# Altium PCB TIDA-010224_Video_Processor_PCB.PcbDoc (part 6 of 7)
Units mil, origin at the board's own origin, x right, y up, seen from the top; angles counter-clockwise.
Board outline 2355.46 x 4164 mil, 10 copper layers (L1-Top Layer, L2-GND, L3-SIG1, L4-GND, L5-PWR, L6-PWR, L7-GND, L8-SIG2, L9-GND, L10-Bottom Layer), stack 62.2 mil thick; 508 components, 274 nets, 3619 pads, 705 vias.
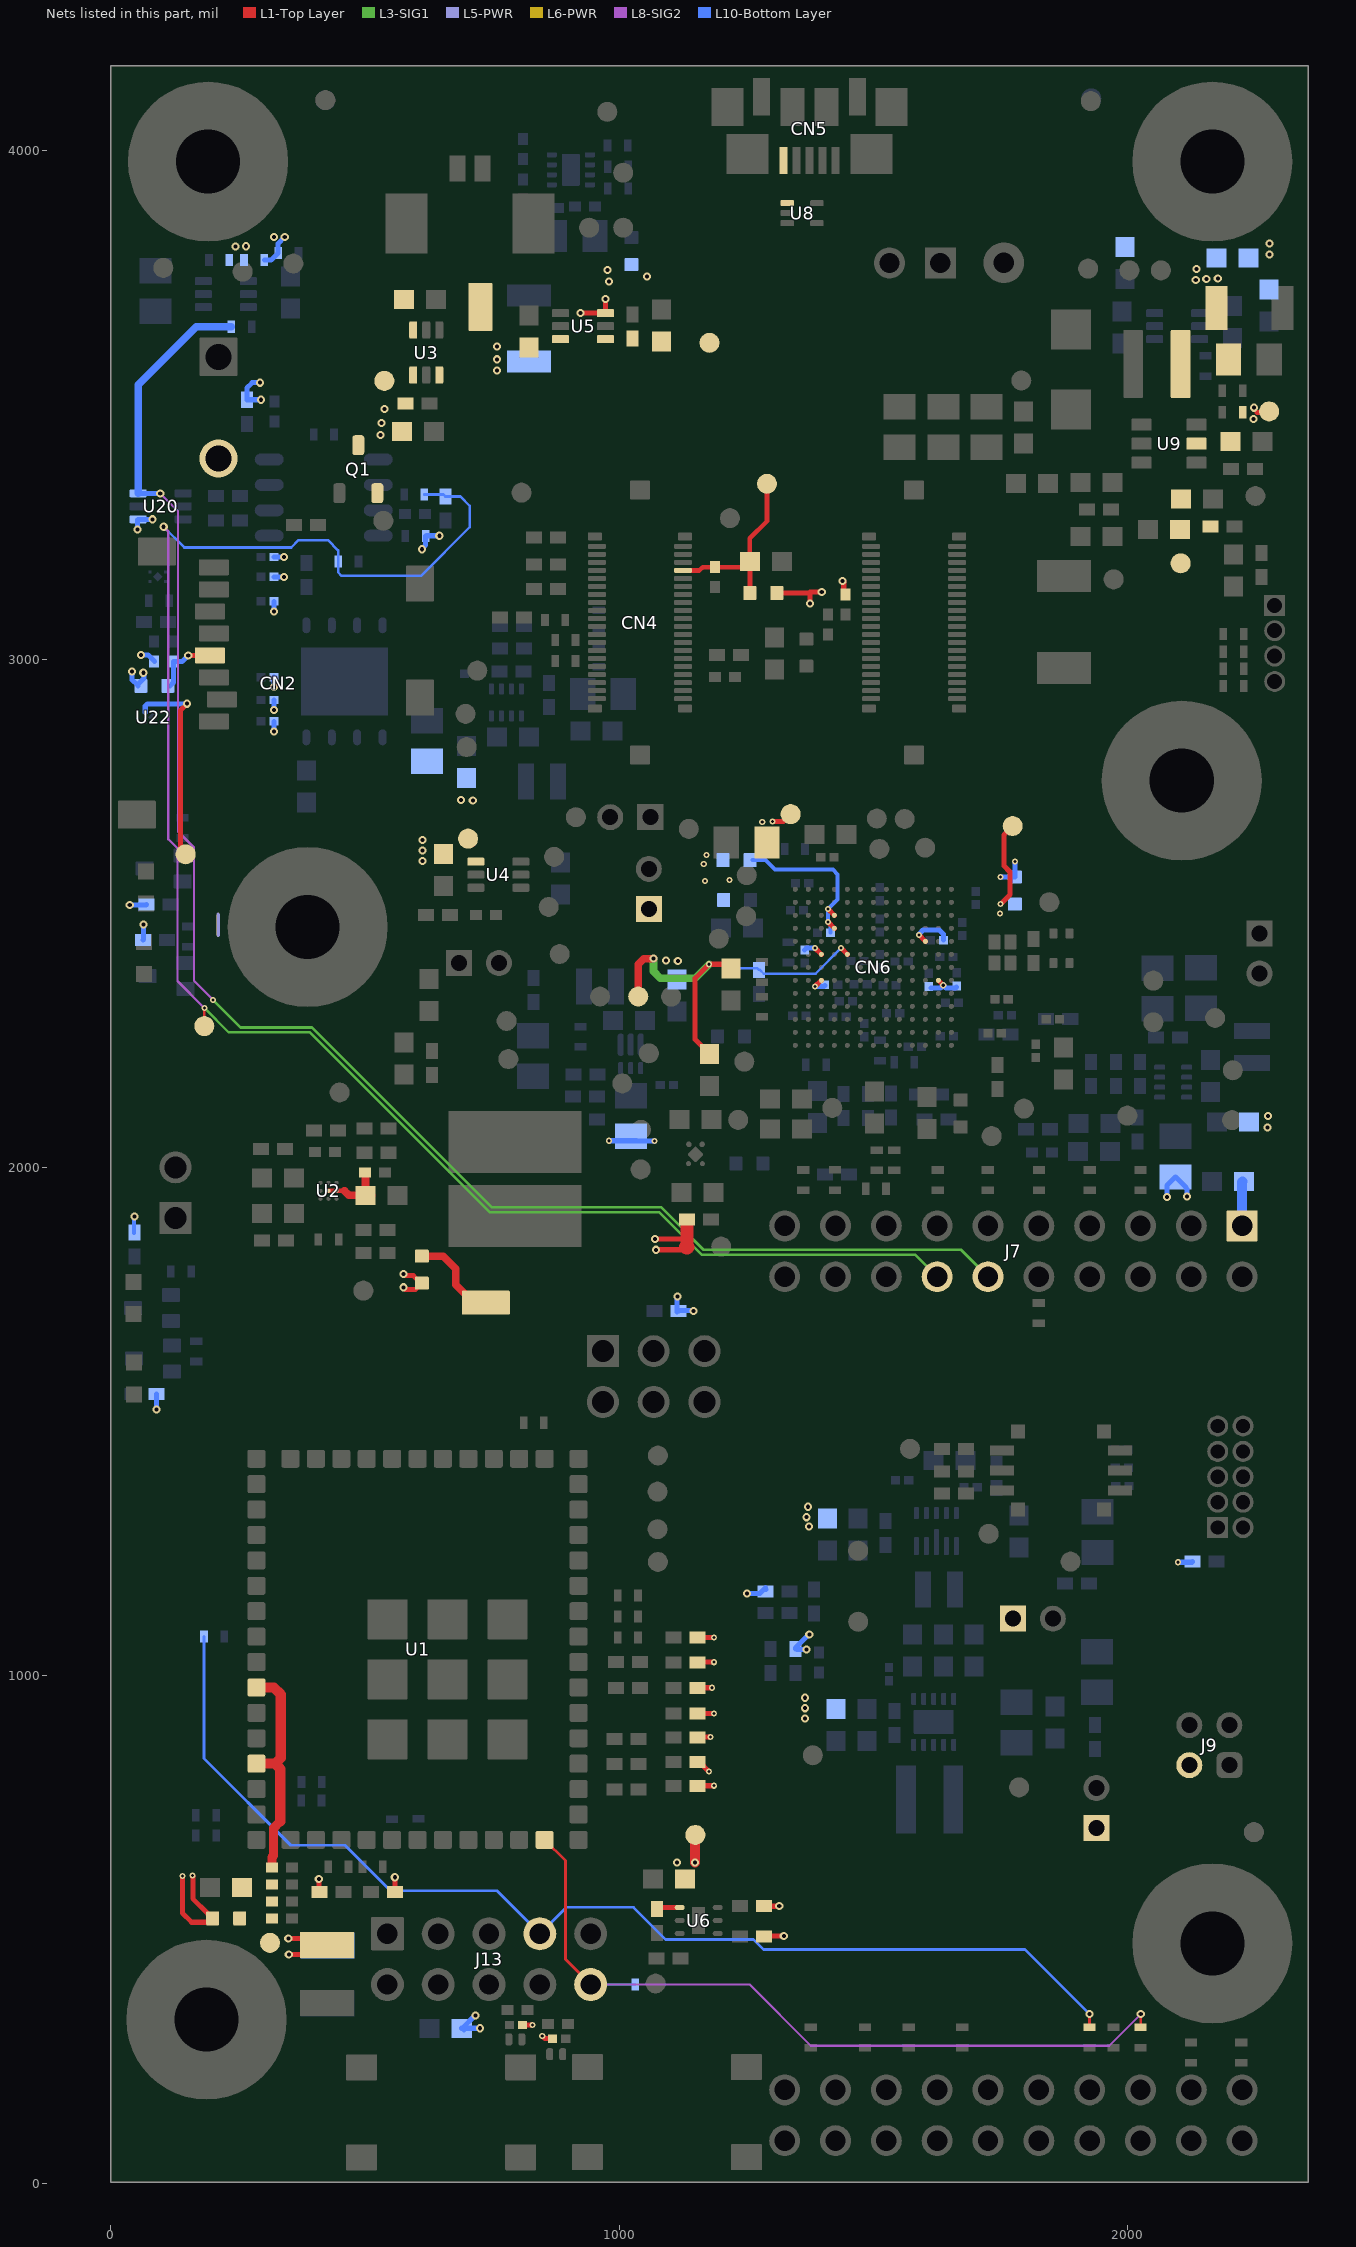
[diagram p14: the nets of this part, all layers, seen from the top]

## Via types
v1: diameter 16, hole 8, L1-Top Layer to L10-Bottom Layer, tented both sides, 414 vias
v2: diameter 12, hole 6, L1-Top Layer to L10-Bottom Layer, tented both sides, 243 vias
v3: diameter 19.68, hole 7.87, L1-Top Layer to L10-Bottom Layer, 44 vias
v4: diameter 14, hole 6, L1-Top Layer to L10-Bottom Layer, tented both sides, 2 vias
v5: diameter 16, hole 8, L1-Top Layer to L10-Bottom Layer, tented top, 1 vias
v6: diameter 20, hole 10, L1-Top Layer to L10-Bottom Layer, tented both sides, 1 vias

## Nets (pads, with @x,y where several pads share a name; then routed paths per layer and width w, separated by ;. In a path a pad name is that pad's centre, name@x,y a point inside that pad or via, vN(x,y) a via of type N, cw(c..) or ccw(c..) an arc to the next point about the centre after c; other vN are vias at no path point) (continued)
V3P3: C41.1 C134.2 FB3.1 FB6.1 FB11.1 FB12.1 J2.1 R182.2 R183.2 | length 404.6
  L1-Top Layer w10: FB3.1@1310.35,3130.18 1374.09,3130.18 1375.77,3131.87 ; v1(1375.77,3109.37) 1375.77,3131.87 ; v1(1398.68,3132) 1375.91,3132 1375.77,3131.87 ; v1@1439.77,3154.77 1441.93,3152.62 1441.93,3128.58 C41.1@1443.27,3127.24
  L5-PWR w6: 210.34,2498.74 211.17,2497.91 211.17,2455.84
  L10-Bottom Layer w10: v1(37,2516) 68.91,2516 R182.2@69.91,2517 ; v1(41.53,2976.03) 41.53,2959.43 FB12.1@53.5,2947.46 ; FB12.1@53.56,2947.46 52,2949.02 65.24,2962.26 v1@65.23,2974.24 ; v1(58.99,3008) 73.27,3008 C134.2@85.52,2995.75 ; R183.2@62.96,2447 64,2448.04 v1(64,2478) ; v2(1750,2571.63) 1750.2,2571.43 FB6.1@1778.52,2571.43 v2@1778.52,2600.79
  other v1: 63.66,2973.3 1439.64,3153.47 980,3742.87 1054.83,3753.11 977.26,3766
  other v2: 1779.24,2601.51
V3P3_Amp: R153.2 R169.2 R174.2 | length 55.1
  L10-Bottom Layer w10: v1@612.36,3217.89 612.69,3217.89 619.25,3224.45 R153.2@619.25,3242.41 619.79,3241.87 620.81,3242.89 v1(646.11,3242.89)
  other v1: 612.07,3216.2 245,3812 266,3812.53
V3P3_MCU: 3.3V_MCU.1 C3.1 C4.2 C5.2 C6.2 C7.1 C24.1 C61.2 C127.1 FB1.2 J7.1 J9.3 R1.1 R6.1 R11.1 R16.2 R22.2 R34.2 R35.1 R36.1 R37.1 R38.1 R39.1 R40.1 R43.1 R44.1 R89.1 R133.1 R151.1 R162.1 R169.1 R185.2 R186.2 R187.2 U1.37 U1.40 U6.1 VCC_ALS.1 | length 1660.8
  L1-Top Layer w10: v1(349,483) 411.87,483 C7.1@424.85,470.02 406.32,451.49 v1(350,451.49) ; v1(409.02,599.83) 409.02,576.22 R6.1@410.76,574.47 ; v1(558.57,603.16) 558.57,574.54 558.86,574.25 R11.1@559.08,574.47 ; R16.2@810.61,312.74 v2@829.55,312.74 ; v2(848.64,291) 853.94,285.7 R22.2@869.02,285.7 R22.2@872.7,285.7 ; R34.2@1074.95,541.06 1077.63,543.74 U6.1@1119.17,543.74 ; R36.1@1147.26,879.26 v2(1179.37,879.26) ; R39.1@1154.62,830 1158,830 v2(1177,811) ; R187.2@1154.62,1075 v2(1186.74,1075) ; R40.1@1154.88,783.26 v2(1187,783.26) ; R37.1@1154.88,925.49 v2(1187,925.49) ; R38.1@1154.88,975.9 1155.78,975 1156.78,976 v2(1183,976) ; R35.1@1154.88,1026.31 v2(1187,1026.31) ; R43.1@1285.24,546.15 1314.71,546.15 v1(1315,546.44) ; R44.1@1285.47,488.56 1286.47,487.56 v1(1323.99,487.56)
  L1-Top Layer w18: C3.1@316.63,622.67 316.63,642.63 320,646 320,700 333,713
  L1-Top Layer w20: U1.40@286.33,826.67 322.8,826.67 ; U1.37@286.33,976.67 320.33,976.67 334,963 334,837.87 322.8,826.67 ; 333,713 333,816.46 322.8,826.67 ; v1(1149.16,632.44) VCC_ALS.1@1149.16,677.35
  L6-PWR w6: 211.18,2495.33 211.18,2457.68 211.61,2457.25
  L10-Bottom Layer w8: R186.2@45.78,1870.98 45.78,1906.47 46,1906.25 v1(46,1903) ; v1(349,483) 421.71,483 C127.1@424.85,479.86 ; v1(350,451.49) 391.49,451.49 392.7,452.7 C127.1@392.7,480.37
  L10-Bottom Layer w10: v1(89.58,1523.76) R185.2@89.58,1553.71 ; R169.1@301.76,3785.12 314.94,3785.12 R162.1@329.04,3799.21 329.04,3818 v1(342.04,3831) ; R151.1@690.28,306 R151.1@691.5,306 ; v1(717,331) 716.5,331 R151.1@691.5,306 ; v1(726,306) 697.5,306 694.5,303 R151.1@691.5,306 ; R133.1@1114.21,1715.35 v1@1114.21,1740.97 ; R133.1@1117.21,1717.35 1118.04,1718.17 1145.18,1718.17 v1(1146.01,1717.35) ; v2(2099.33,1223) 2127.41,1223 R89.1@2128.41,1224
  L10-Bottom Layer w20: J7.1@2225.78,1884.79 2225.78,1971.5 C61.2@2226.43,1972.15
  other v1: 1113.95,632.44 1114.59,1745.9 320.53,3831
  other v2: 829.55,312.24
V3P3_OV: C79.2 C82.2 C83.2 C100.2 C107.2 CN6.F2 CN6.F11 CN6.H11 CN6.J3 FB6.2 FB8.1 FB9.1 OV_3.3V.1 | length 405.2
  L1-Top Layer w10: v2(1385.59,2355.77) CN6.F11@1397.82,2368 ; v2(1385.59,2431.41) CN6.H11@1397.82,2419.18 ; v2(1590.32,2457) CN6.J3@1602.54,2444.77 ; CN6.F2@1628.13,2368 v2(1637.77,2358.36) ; v2(1750.34,2517.85) 1769.07,2536.58 1769.07,2581.41 1757.06,2593.42 1757.06,2654.33 OV_3.3V.1@1774.34,2671.61
  L10-Bottom Layer w10: C107.2@1365,2427.99 1368.42,2431.41 v2(1385.59,2431.41) ; v2(1385.59,2355.77) 1402.78,2355.77 C100.2@1405.01,2358 ; v2(1590.32,2457) 1590.32,2459.36 1597.98,2467.03 1629.64,2467.03 1637.99,2458.68 C82.2@1637.99,2447 ; C83.2@1614,2353.01 1632.42,2353.01 v2(1637.77,2358.36) 1643.19,2352.94 1661.93,2352.94 C79.2@1664,2355.01
  other v2: 1749,2499.59 1168.73,2563.6 1216.75,2565.46 1166.46,2596.89 1172,2615
V3P3_PA: 3.3V_PA.1 C9.1 C12.2 FB2.2 U2.B1 U2.B2 | length 308.2
  L1-Top Layer w8: U2.B2@428.07,1953.93 U2.B1@443.82,1953.93 459.47,1953.93
  L1-Top Layer w15: 459.47,1953.93 468.4,1945 C9.1@485,1945 ; C9.1@500.96,1950.4 C12.2@500.96,1983.17 ; FB2.2@611.6,1825.15 653.59,1825.15 678.16,1800.58 678.16,1769.21 713.61,1733.76 3.3V_PA.1@737.57,1733.76 ; C9.1@496.71,1944.34 513.02,1944.34 C9.1@496.71,1944.34
V3P3_SC: 3.3V_SC.1 C131.2 CN2.4 FB12.2 R163.2 R164.2 R165.2 R166.2 R167.2 R168.2 U22.4 | length 647.5
  L1-Top Layer w10: 3.3V_SC.1@146.92,2616 137,2625.92 137,2899.33 v1(150,2912.33) ; v1(152.16,3007.36) CN2.4@194.65,3007.36
  L10-Bottom Layer w10: U22.4@67.52,2895.44 67.52,2907.35 72.17,2912 149.67,2912 v1(150,2912.33) ; FB12.2@116.52,2947.44 123,2953.91 123,2995 139.8,2995 v1(152.16,3007.36) ; v1(321,2858) R166.2@321,2877.71 ; v1(321,2900) R165.2@321,2919.71 ; v1(321,2945) R164.2@321,2964.71 ; v1(321,3094) R163.2@321,3113.71 ; R168.2@320.99,3162 v1(340.7,3162) ; R167.2@320.99,3201 v1(340.7,3201)
V3P3_SN_AVDD: AVDD.1 C30.1 C34.1 CN4.8 FB3.2 | length 368
  L1-Top Layer w9: CN4.8@1125.65,3174.49 1157.79,3174.49 1164.3,3181 1245.17,3181 C34.1@1257.2,3193.03 ; C34.1@1257.2,3192.03 C34.1@1257.2,3193.03 ; AVDD.1@1290.89,3345 1290.89,3271.56 1257.2,3237.87 C34.1@1257.2,3193.03
  L1-Top Layer w10: FB3.2@1257.2,3130.18 C34.1@1257.2,3192.03
V3P3A: C18.1 FB1.1 FB2.1 IN_3.3V.1 J4.1 J10.1 R127.2 R128.2 U4.1 | length 449.2
  L1-Top Layer w10: v2(140.47,606) 140.47,533.03 158.86,514.64 192.07,514.64 192.31,514.88 192.92,514.88 FB1.1@200.22,522.18 199.61,522.18 189.79,532 189.79,532.4 161.14,561.05 161.14,605.21 v2(160.1,606.24) ; v1(575.32,1764) 579.32,1760 599.6,1760 FB2.1@608.29,1768.69 ; v1(575.32,1790.31) 578.76,1786.87 594.87,1786.87 609.73,1772 FB2.1@611.6,1772 ; IN_3.3V.1@702.69,2646.83 IN_3.3V.1@712.99,2636.53
  L10-Bottom Layer w10: v1(1251.51,1161.38) 1276.61,1161.38 R128.2@1286.47,1171.23 ; R128.2@1288,1172.76 R128.2@1286.47,1171.23 ; R128.2@1288.73,1168.97 R128.2@1286.47,1171.23 ; R127.2@1346.84,1052.47 R127.2@1346.84,1054.66 ; v1(1368.79,1051.66) 1350.21,1051.66 1350.03,1051.47 R127.2@1346.84,1054.66 ; v1(1374.19,1080.66) 1372.84,1080.66 R127.2@1346.84,1054.66
  other v1: 613,2602.79 613,2623.79 613,2644
V_POWER: C57.1 C58.1 L1.1 R88.2 R95.2
  other v1: 2134.51,3746.1 2155.33,3747.73 2177.98,3749.15 2136.25,3767.97
V_VBAT: BAT.1 C13.1 C16.1 Q1.2 U3.1 U5.3 U20.1 | length 125.5
  L1-Top Layer w10: v1(924,3681) 973.17,3681 v1(973.17,3708.76)
  L10-Bottom Layer w10: v1(52.41,3255) 52.41,3274.1 U20.1@53.49,3275.17 v1(81.49,3275.17)
  other v1: 530.17,3440.79 532.14,3465 538.42,3492
VBAT: C14.1 C21.1 C59.2 C119.1 R41.2 R79.2 R86.1 R87.1 R88.1 R91.2 R123.1 R124.1 R134.1 R137.2 R150.1 R152.2 R170.2 U3.6 U5.6 U9.5 VBAT.1 VP.1 | length 457.9
  L1-Top Layer w10: v1(1070.63,1859.05) 1126.13,1859.05 ; v1(1072.29,1837.83) 1127.79,1837.83 1133.02,1843.06 ; 2255,3485 2276.55,3485 VP.1@2279,3487.45
  L1-Top Layer w25: 1133.38,1843.42 R41.2@1133.38,1892.09
  L1-Top Layer w30: 1133.02,1843.06 1133.38,1843.42
  L10-Bottom Layer w10: v1(293.23,3544) 278.05,3544 267.38,3533.33 R170.2@267.38,3510.43 v1(295.38,3510.43) ; v2(980,2052.38) 1033.62,2052.38 1034,2052 v2(1069.58,2052) ; v1@2077.97,1941.33 2077.97,1964.61 R91.2@2094.44,1981.08 ; R91.2@2095,1981.08 2115.73,1960.36 2115,1959.63 2117,1957.63 v1(2117,1943)
  other v1: 1365.39,915.34 1365.87,935.79 1365.87,956.34 1373.88,1293.21 1368.88,1311.66 1371.88,1332.21 2077.67,1941.33 2275.74,2078.29 2276.74,2101.29 1092.41,2407 1115.41,2406.29 712,2722 689,2723 2248.31,3472.3 2249,3494.8 760,3568 760,3590 760,3615 2279.5,3795.88 2280,3818
VBAT_Gauge: C125.1 J7.27 MEAS_MCU.1 R154.2 R157.2 | length 3536.2
  L1-Top Layer w5.5: MEAS_MCU.1@183.72,2278 v2(183.72,2313.83)
  L3-SIG1 w5: v2(183.72,2313.83) 231.84,2265.7 391.39,2265.7 745.15,1911.94 1078.52,1911.94 1162.3,1828.17 1582.39,1828.17 J7.27@1625.78,1784.79
  L8-SIG2 w4.5: v1(103.83,3260.54) 113,3251.37 113,2645.76 131,2627.76 131,2366.54 v2(183.72,2313.83)
  L10-Bottom Layer w5: v1(103.83,3260.54) 144.65,3219.72 354.84,3219.72 369.45,3234.33 426.67,3234.33 447,3214 R157.2@447,3192 447,3171 454,3164 610.25,3164 706,3259.75 706,3301.54 687.51,3320.03 C125.1@658.25,3320.03 654.28,3324.01 R154.2@616.81,3324.01
VBAT_Meas: J7.26 R171.1 U20.3 | length 3277.9
  L3-SIG1 w5.5: v2(201.11,2329.14) 254.8,2275.45 395.43,2275.45 749.19,1921.69 1082.56,1921.69 1166.33,1837.92 1586.43,1837.92 1586.5,1837.86 1672.71,1837.86 J7.26@1725.78,1784.79
  L8-SIG2 w4.5: v1(97,3326) 131.93,3291.07 131.93,2660.91 163.25,2629.59 163.25,2367 v2(201.11,2329.14)
  L10-Bottom Layer w10: U20.3@53.49,3326.35 53.84,3326 v1(97,3326)
  L10-Bottom Layer w15: U20.3@53.49,3326.35 54,3326.87 54,3540 168,3654 R171.1@237,3654
VBAT_Primary: J1.2 Q1.3
VDDAO: C31.2 C101.2 CN6.K10 CN6.L10 FB9.2 VDDAO.1 | length 379.8
  L1-Top Layer w10: v2(1301.74,2680.48) 1322.86,2680.48 VDDAO.1@1337.44,2695.06 ; v2(1411.18,2482.59) CN6.K10@1423.41,2470.36 ; v2(1411.18,2508.18) CN6.L10@1423.41,2495.95
  L10-Bottom Layer w8: FB9.2@1262.5,2604.55 1288.18,2604.55 1306.6,2586.13 1420.45,2586.13 1430,2576.57 1430,2527 v2(1411.18,2508.18) v2(1411.18,2482.59) 1416.06,2477.71 C101.2@1416.06,2462
  other v2: 1281.62,2679.93
VEFUSE: C33.1 CN6.H9 R42.2 R132.2 VeFuse.1 | length 799.4
  L1-Top Layer w10: R42.2@1178.12,2223.08 1149.65,2251.56 1149.65,2372.35 v2(1176.98,2399.69) 1212.45,2399.69 C33.1@1220.46,2391.68 ; v2(1436.77,2431.41) CN6.H9@1449,2419.18
  L1-Top Layer w15: VeFuse.1@1037.58,2336.15 1037.58,2400.01 1048.26,2410.69 v1(1067.56,2410.69)
  L3-SIG1 w15: v1(1067.56,2410.69) 1067.56,2386.17 1081.28,2372.45 1149.74,2372.45 v2(1176.98,2399.69)
  L10-Bottom Layer w5: v2(1176.98,2399.69) 1177.98,2398.69 1227.74,2398.69 1234.74,2391.68 1271.87,2391.68 R132.2@1274.94,2388.62 ; R132.2@1276.94,2388.62 1284.58,2380.98 1386.34,2380.98 v2(1436.77,2431.41)
VREF: C56.2 R72.1 R76.2 REF.1
VUSB_5V: C23.1 C25.1 CN5.1 U3.3 U5.1 U8.1 USB.1
WIFI_CONFIG: J13.10 R73.1 R136.1 U1.54 | length 1591
  L1-Top Layer w5.5: U1.54@853.26,676.7 894.19,635.77 894.19,441.81 J13.10@944,392 ; R73.1@2025.59,310.73 2026.3,311.44 v1(2026.3,333.73)
  L8-SIG2 w4.5: J13.10@944,392 1256.83,392 1377.02,271.81 1964.39,271.81 v1(2026.3,333.73)
  L10-Bottom Layer w4.5: J13.10@944,392 R136.1@1031.7,392
WIFI_nRESET: J13.7 R69.1 R175.1 | length 2259
  L1-Top Layer w5.5: R69.1@1925.78,308.7 v1(1925.78,333.73)
  L10-Bottom Layer w5.5: R175.1@183.09,1076.67 183.09,836.91 353.88,666.12 460.67,666.12 550.15,576.64 759.36,576.64 J13.7@844,492 896,544 1028,544 1091.38,480.62 1264.38,480.62 1284,461 1798.51,461 v1(1925.78,333.73)
pads on no net: CN3.3 CN3.4 CN4. CN4.3 CN4.4 CN4.6 CN4.10 CN4.11 CN4.12 CN4.13 CN4.15 CN4.27 CN4.29 CN4.31 CN4.33 CN4.35 CN4.37 CN5.4 CN6.A5 CN6.B3 CN6.B9 CN6.C6 CN6.D10 CN6.D11 CN6.D12 CN6.E10 CN6.E11 CN6.E12 CN6.E13 CN6.F10 CN6.F12 CN6.G10 CN6.G12 CN6.G13 CN6.H10 CN6.H12 CN6.H13 CN6.J10 CN6.J11 CN6.J12 CN6.J13 CN6.K7 CN6.K8 CN6.K13 CN6.L4 CN6.L5 CN6.M4 CN6.M5 CN6.M7 CN6.M8 CN6.N4 CN6.N5 CN6.N7 CN6.N8 CN7. CN7.1 CN7.2 CN7.3 CN7.4 CN7.5 CN7.6 CN7.7 CN7.8 CN7.9 CN7.10 CN7.11 CN7.12 CN7.13 CN7.14 CN7.15 CN7.16 CN7.17 CN7.18 CN7.19 CN7.20 CN7.21 CN7.22 CN7.23 CN7.24 CN7.25 CN7.26 CN7.27 CN7.28 CN7.29 CN7.30 CN7.31 CN7.32 CN7.33 CN7.34 CN7.35 CN7.36 CN7.37 CN7.38 CN7.39 CN7.40 D5.1S D5.2S D6.1S D6.2S FID1.1 FID2.1 FID3.1 FID6.1 FID6_1.1 FID6_2.1 H1.1 H2.1 H3.1 H4.1 H5.1 H6.1 H7.0 H8.0 H9.0 H10.0 H11.0 H12.0 J5.10 J7.2 J7.21 J7.23 J7.24 J7.28 J7.29 J7.30 J8.11 J8.16 J8.17 J8.19 J8.31 J8.32 J8.33 J8.34 J8.35 J8.36 LBL1.0 SW3.M1 SW3.M2 SW3.M3 SW3.M4 U1.20 U1.31 U1.33 U1.39 U1.41 U1.45 U1.55@758.77,896.15 U1.55@802.08,896.15 U1.56@758.77,970.96 U1.56@758.77,1014.26 U1.56@802.08,970.96 U1.56@802.08,1014.26 U1.57@758.77,1089.07 U1.57@758.77,1132.37 U1.57@802.08,1089.07 U1.57@802.08,1132.37 U1.58@640.66,852.85 U1.58@640.66,896.15 U1.58@683.97,852.85 U1.58@683.97,896.15 U1.59@640.66,970.96 U1.59@640.66,1014.26 U1.59@683.97,970.96 U1.59@683.97,1014.26 U1.60@640.66,1089.07 U1.60@640.66,1132.37 U1.60@683.97,1089.07 U1.60@683.97,1132.37 U1.61@522.55,852.85 U1.61@522.55,896.15 U1.61@565.86,852.85 U1.61@565.86,896.15 U1.62@522.55,970.96 U1.62@522.55,1014.26 U1.62@565.86,970.96 U1.62@565.86,1014.26 U1.63@522.55,1089.07 U1.63@522.55,1132.37 U1.63@565.86,1089.07 U1.63@565.86,1132.37 U3.4 U4.4 U5.4 U8.2 U10.4 U10.5 U11.4 U13.11@1597.54,908.87 U13.11@1640.46,908.87 U14.4@1003.11,2241.47 U14.5@1022.79,2241.47 U14.6@1042.48,2241.47 U15.9@905,3945.26 U15.9@905,3980.69 U16.4 U18.1 U18.5 U18.8 U19.4 U19.5 U20.4 U20.5
copper on no net: | length 1.4
  L1-Top Layer w5.5: 1325,185.57 1325.78,184.79 ; 1625.78,184.79 1626,185.01

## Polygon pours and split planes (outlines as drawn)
GND on L10-Bottom Layer "L10-BOTTOM_LAYER_GND_P594" (solid, remove dead copper, pour order 594): 2313.77,36.98 13.27,36.98 13.27,4076.27 87,4150 2240.45,4150 2325.78,4064.67 2325.78,48.99
V1P1_OV on L10-Bottom Layer "L10-BOTTOM_LAYER_V1P1_OV_P508" (solid, pour order 508): 1268.7,2031.58 1268.7,1984.05 1278.03,1974.72 1346.33,1974.72 1389.16,2017.55 1389.16,2037.44 1378.71,2047.9 1285.01,2047.9
no net on L10-Bottom Layer "L10-BOTTOM_LAYER_NONET_P647" (solid, pour order 647): 4363.73,1594.74
no net on L10-Bottom Layer "L10-BOTTOM_LAYER_NONET_P645" (solid, pour order 645): 4364.19,1621.74
no net on L10-Bottom Layer "L10-BOTTOM_LAYER_NONET_P643" (solid, pour order 643): 4358.58,1625.36
no net on L10-Bottom Layer "L10-BOTTOM_LAYER_NONET_P641" (solid, pour order 641): 4363.19,1628.07
NetC69_2 on L10-Bottom Layer "L10-BOTTOM_LAYER_NETC69_2_P521" (solid, pour order 521): 1954.38,2182.14 1953.88,2181.64 1917.34,2181.64 1912.25,2176.55 1912.25,2145.17 1918.66,2138.77 1949.99,2138.77 2036.32,2138.77 2047.85,2150.29 2075.11,2150.29 2077.11,2152.29 2077.11,2163.29 2074.11,2166.29 2017.69,2166.29 2001.85,2182.14
PG_1V8 on L10-Bottom Layer "L10-Bottom Layer-PG_1V8" (solid, remove dead copper, pour order 629): 752.46,2877 657.44,2877 655.56,2875.11 655.56,2854.28 654.28,2853 572.06,2853 568,2857.06 568,2922.93 576.07,2931 648.78,2931 677,2902.78 752.39,2902.78 754,2901.17 754,2878.29 753,2877.29
no net on L10-Bottom Layer "L10-Bottom Layer-No Net" (solid, remove dead copper, pour order 614): 1497,2238.5 1488.5,2247 1470.18,2247 1468.99,2245.81 1468.99,2218.38 1476.05,2211.32 1538.25,2211.32 1538.5,2211.57 1538.5,2237.25 1533.74,2242 1503.22,2242 1498.22,2247 1488,2247
no net on L10-Bottom Layer "L10-Bottom Layer-No Net 1" (solid, remove dead copper, pour order 613): 1533.96,2294.92 1577.89,2294.92 1578.4,2294.41 1578.4,2258.57 1576.63,2256.8 1525.12,2256.8 1519.77,2262.16 1519.77,2296.3 1520,2296.52 1521.67,2294.86 1535,2294.86
V_POWER on L10-Bottom Layer "L10-BOTTOM_LAYER_V_POWER_P583" (solid, pour order 583): 2027,3833.07 2042.66,3833.07 2061.35,3814.38 2193.04,3814.38 2200.89,3806.53 2200.89,3755.5 2178.55,3733.29 2064.34,3733.29 2021.7,3775.94 1964.48,3775.94 1950.26,3790.16 1950.26,3817.35 1965.98,3833.07
VBAT on L10-Bottom Layer "L10-BOTTOM_LAYER_VBAT_P561" (solid, pour order 561): 2299.03,3709.25 2302.78,3713 2302.78,3754.11 2301.7,3755.19 2301.7,3820.09 2296,3826 2225,3826 2217.75,3818.75 2217.75,3750.97 2259.47,3709.25
NetC111_1 on L10-Bottom Layer "L10-Bottom Layer-NetC104_1" (solid, remove dead copper, pour order 599): 849,2957.18 849,2926.19 850.19,2925 877.16,2925 903,2899.16 953.13,2899.16 954,2900.03 954,2962.45 952.45,2964 880,2964 874,2958 849.82,2958
NetC65_1 on L10-Bottom Layer "L10-Bottom Layer-NetC97_1" (solid, remove dead copper, pour order 598): 2030.4,2350.82 2028,2348.42 2028,2256 2035.06,2248.94 2076.7,2248.94 2077,2249.24 2077,2282.44 2096,2301.44 2096,2349.82 2095,2350.82
NetC73_1 on L10-Bottom Layer "L10-BOTTOM_LAYER_NETC73_1_P533" (solid, pour order 533): 1746.53,1209.57 1795.92,1209.57 1819.49,1186 1819.49,1076.98 1826.13,1070.34 1887.81,1070.34 1895.17,1077.71 1895.17,1266.76 1883.91,1278.01 1660.23,1278.01 1655.3,1273.09 1655.3,1237.55 1667.14,1225.71 1730.39,1225.71
NetC70_1 on L10-Bottom Layer "L10-BOTTOM_LAYER_NETC70_1_P513" (solid, remove dead copper, pour order 513): 17 vertices, not listed, extent 1652.04,753.02 1968,897.31
V3P3_MCU on L10-Bottom Layer "L10-Bottom Layer-V3P3_MCU" (solid, remove dead copper, pour order 504): 291.06,3772.17 293.23,3770 322.98,3770 353.57,3800.6 353.57,3842.54 350.04,3846.07 314.28,3846.07 291.06,3822.85
VDDAO on L10-Bottom Layer "L10-BOTTOM_LAYER_VDDAO_P579" (solid, pour order 579): 1261.85,2582 1244,2582 1237,2589 1237,2686.7 1300.65,2686.7 1307.19,2680.16 1307.19,2594.3 1294.89,2582 1244,2582
V3P3_OV on L10-Bottom Layer "L10-BOTTOM_LAYER_V3P3_OV_P507" (solid, pour order 507): 1160.93,2614.72 1172.21,2626 1217,2626 1223,2620 1223,2565.46 1223,2506.65 1213.82,2497.47 1165.45,2497.47 1160.93,2501.99
V3P3_Amp on L10-Bottom Layer "L10-Bottom Layer-V3P3_Amp" (solid, remove dead copper, pour order 506): 220,3774.43 223,3771.43 270.22,3771.43 277.26,3778.47 277.26,3816.86 274.12,3820 225,3820 220,3815
NetC129_2 on L10-Bottom Layer "L10-BOTTOM_LAYER_NETC129_2_P550" (solid, pour order 550): 299.08,3756.65 314.72,3756.65 350.98,3792.9 350.98,3811.74 358.45,3819.21 384.54,3819.21 405,3798.75 405,3733.11 400.89,3729 298.23,3729 293.23,3734 253.72,3734 249.27,3738.46 249.27,3751.42 254.49,3756.65
V3P3 on L10-Bottom Layer "L10-BOTTOM_LAYER_V3P3_P582" (solid, pour order 582): 1745.27,2609.27 1794.27,2609.27 1803.45,2600.08 1803.45,2552.86 1798.69,2548.09 1750,2548.09 1740.69,2557.4 1740.69,2604.69
NetL5_1 on L10-Bottom Layer "L10-BOTTOM_LAYER_NETL5_1_P510" (solid, pour order 510): 19 vertices, not listed, extent 976,2214.89 1048.25,2402.63
NetC114_2 on L10-Bottom Layer "L10-BOTTOM_LAYER_NETC114_2_P509" (solid, pour order 509): 988.8,2202.73 949.18,2202.73 943.82,2197.38 943.82,2081.28 945.11,2080 975,2080 978.31,2083.31 978.31,2166.81 993.81,2182.31 1006.99,2182.31 1011.03,2186.35 1011.03,2208.3 1008.92,2210.42 996.47,2210.42 995.54,2209.46
NetL4_2 on L10-Bottom Layer "L10-BOTTOM_LAYER_NETL4_2_P534" (solid, pour order 534): 1654.96,1201.17 1654.96,1134.11 1662.39,1126.69 1675.17,1126.69 1683.3,1134.81 1683.3,1201.93 1670.02,1215.21 1651.89,1233.35 1651.88,1273.67 1648.88,1276.67 1638.88,1276.67 1636.88,1274.67 1636.88,1219.24
NetC126_2 on L10-Bottom Layer "L10-BOTTOM_LAYER_NETC126_2_P591" (solid, remove dead copper, pour order 591): 491.7,3304.34 561.37,3304.34 565.76,3308.74 594.55,3308.74 598.32,3304.97 598.32,3238.94 588.73,3229.35 570.4,3229.35 562.69,3237.06 562.69,3270.65 551.75,3281.6 495.64,3281.6 491.7,3285.54
NetC62_1 on L10-Bottom Layer "L10-BOTTOM_LAYER_NETC62_1_P511" (solid, pour order 511): 2261.84,3636.02 2298.21,3636.02 2306.34,3644.15 2306.34,3680.55 2299.66,3687.23 2253.57,3687.23 2219.74,3721.05 2171.23,3721.05 2125.48,3721.05 2118.46,3714.03 2118.46,3681.13 2126.96,3672.63 2225.23,3672.62
NetC68_1 on L10-Bottom Layer "L10-BOTTOM_LAYER_NETC68_1_P512" (solid, remove dead copper, pour order 512): 1978.87,906.46 1978.87,996.16 1965.11,1009.92 1906.26,1009.92 1896.17,999.83 1896.17,902.8 1911.84,887.14 1959.55,887.14
NetC110_1 on L10-Bottom Layer "L10-BOTTOM_LAYER_NETC110_1_P515" (solid, pour order 515): 1081.62,2278.3 1054.36,2251.04 1054.36,2229 1054.28,2220.49 1049.37,2215.59 1038.85,2215.59 1035.21,2219.23 1035.21,2310.19 1054.01,2329 1124.63,2329 1127.63,2326 1127.59,2284.3 1121.59,2278.3
Net1.8V_1 on L10-Bottom Layer "L10-BOTTOM_LAYER_NET1.8V_1_P530" (solid, pour order 530): 17 vertices, not listed, extent 849,2663 1013,2912
V3P3_OV on L10-Bottom Layer "L10-BOTTOM_LAYER_V3P3_OV_P580" (solid, pour order 580): 1796.52,2483.61 1745.52,2483.61 1740.75,2488.37 1740.75,2530.84 1745.52,2535.61 1794.21,2535.61 1803.52,2526.3 1803.52,2490.61
V3P3 on L10-Bottom Layer "L10-BOTTOM_LAYER_V3P3_P577" (solid, pour order 577): 968.5,3772.5 986,3790 1056.6,3790 1066.36,3780.23 1066.36,3741.58 1055.78,3731 976.22,3731 968.5,3738.72
NetC113_1 on L10-Bottom Layer "L10-BOTTOM_LAYER_NETC113_1_P572" (solid, pour order 572): 35 vertices, not listed, extent 780.11,3768 1049,3941.32
no net on L10-Bottom Layer "L10-BOTTOM_LAYER_NONET_P569" (solid, pour order 569): 2081,3507
VBAT on L10-Bottom Layer "L10-BOTTOM_LAYER_VBAT_P567" (solid, pour order 567): 872.19,3603.6 872.19,3566.19 861,3555 756.93,3555 748,3563.93 748,3619 756.17,3627.17 865.54,3627.17 872.01,3620.7
GND on L10-Bottom Layer "L10-BOTTOM_LAYER_GND_P566" (solid, pour order 566): 874.19,3739.43 874.19,3694.43 866.76,3687 779.71,3687 773.95,3692.76 773.95,3747.95 785.76,3759.76 863.61,3759.76 874.09,3749.28
no net on L10-Bottom Layer "L10-BOTTOM_LAYER_NONET_P563" (solid, pour order 563): 160,3437.6
GND on L10-Bottom Layer "L10-BOTTOM_LAYER_GND_P505" (solid, pour order 505): 48.06,3702.83 59.06,3713.83 120.17,3713.83 128,3706 128,3644.5 113.5,3630 61.56,3630 48.06,3643.5
NetC133_1 on L10-Bottom Layer "L10-BOTTOM_LAYER_NETC133_1_P558" (solid, pour order 558): 201.92,3805 208.5,3798.42 208.5,3733.58 205.98,3731.06 201.29,3731.29 201,3731 44.65,3731 22,3753.65 22,3787 40,3805
GND on L10-Bottom Layer "L10-BOTTOM_LAYER_GND_P597" (solid, pour order 597): 249.27,3722.69 254.57,3728 287.56,3728 294.56,3721 371.83,3721 381.54,3711.29 381.54,3648.54 370.55,3637.56 328.45,3637.56 313,3653 313,3696.23 304.06,3705.18 254.82,3705.18 249.05,3710.95
NetC87_1 on L10-Bottom Layer "L10-BOTTOM_LAYER_NETC87_1_P546" (solid, pour order 546): 1365.47,898.41 1359.05,892 1359.05,828.61 1373.67,814 1480.16,814 1497,830.85 1569.84,830.85 1585,846.01 1585,877 1563.59,898.41
NetC89_1 on L10-Bottom Layer "L10-BOTTOM_LAYER_NETC89_1_P545" (solid, pour order 545): 1589.08,1274.42 1507.79,1274.42 1501.84,1268.47 1385.84,1268.47 1376.95,1259.58 1376.95,1220.87 1387.58,1210.24 1530.31,1210.24 1554.93,1234.86 1589.66,1234.86 1593.54,1238.74 1593.54,1269.95
no net on L10-Bottom Layer "L10-BOTTOM_LAYER_NONET_P544" (solid, pour order 544): 3837.39,1826.07
no net on L10-Bottom Layer "L10-BOTTOM_LAYER_NONET_P543" (solid, pour order 543): 3832.78,1823.36
no net on L10-Bottom Layer "L10-BOTTOM_LAYER_NONET_P542" (solid, pour order 542): 3838.39,1819.74
no net on L10-Bottom Layer "L10-BOTTOM_LAYER_NONET_P541" (solid, pour order 541): 966.3,2045.65
VBAT on L10-Bottom Layer "L10-BOTTOM_LAYER_VBAT_P540" (solid, pour order 540): 1453.39,907.34 1453.39,955.14 1443.66,964.87 1360.91,964.87 1355.71,959.68 1355.71,912.41 1360.78,907.34
no net on L10-Bottom Layer "L10-BOTTOM_LAYER_NONET_P539" (solid, pour order 539): 3843.1,2068.08
NetL3_2 on L10-Bottom Layer "L10-BOTTOM_LAYER_NETL3_2_P538" (solid, pour order 538): 1631.71,835.76 1637,830.47 1637,687.03 1641.12,682.92 1678.52,682.92 1685.2,689.6 1685.2,816.44 1675.78,825.86 1646.71,854.92 1646.71,874.03 1644.41,876.33 1634.01,876.33 1631.71,874.08
NetL3_1 on L10-Bottom Layer "L10-BOTTOM_LAYER_NETL3_1_P537" (solid, pour order 537): 1577.8,836.02 1568.39,826.6 1544.53,826.6 1536.84,818.92 1536.84,692.73 1545.76,683.81 1582.56,683.81 1591.66,692.9 1591.66,826.04 1606.69,841.07 1606.69,874.78 1604.42,877.05 1594.69,877.05 1592.05,874.31 1592.05,850.26
NetC67_1 on L10-Bottom Layer "L10-BOTTOM_LAYER_NETC67_1_P536" (solid, pour order 536): 1905.87,1150.51 1905.87,1269.69 1913.69,1277.51 1972.24,1277.51 1979.8,1269.95 1979.8,1163.44 1966.87,1150.51
NetL4_1 on L10-Bottom Layer "L10-BOTTOM_LAYER_NETL4_1_P535" (solid, pour order 535): 1611.88,1249.21 1611.88,1218.22 1627.29,1202.82 1627.29,1136.59 1616.79,1126.09 1595.21,1126.09 1585.08,1136.22 1585.08,1202.08 1597.22,1214.22 1597.22,1273.59 1598.84,1275.21 1608.88,1275.21 1611.89,1272.21
no net on L10-Bottom Layer "L10-BOTTOM_LAYER_NONET_P532" (solid, pour order 532): 3837.93,1792.74
VBAT on L10-Bottom Layer "L10-BOTTOM_LAYER_VBAT_P531" (solid, pour order 531): 1428.87,1284.51 1428.87,1331.25 1419.91,1340.21 1368.67,1340.21 1360.89,1332.43 1360.89,1292.18 1368.56,1284.51
NetC121_1 on L10-Bottom Layer "L10-BOTTOM_LAYER_NETC121_1_P528" (solid, pour order 528): 775.99,2897.66 775.99,2831.99 750.57,2806.57 679.95,2806.57 676.95,2809.57 676.99,2851.27 682.99,2857.27 743.35,2857.27 760.98,2874.9 760.98,2897.56 764.99,2901.57 772.37,2901.57
NetC122_2 on L10-Bottom Layer "L10-BOTTOM_LAYER_NETC122_2_P526" (solid, pour order 526): 787.97,2998.32 787.97,3069.39 784.44,3073 751.16,3073 749.46,3071.3 749.46,2968.71 760.99,2957.18 760.99,2929.92 762.99,2927.92 773.99,2927.92 776.99,2930.92 776.99,2987.34
VBAT on L10-Bottom Layer "L10-BOTTOM_LAYER_VBAT_P529" (solid, pour order 529): 603.33,2713 596.74,2713 588,2721.74 588,2823 591.21,2826.21 655.56,2826.21 657,2824.77 657,2806.98 677.8,2786.18 723.52,2786.18 731.99,2777.71 731.99,2720.14 724.86,2713 674.34,2713
NetL6_1 on L10-Bottom Layer "L10-BOTTOM_LAYER_NETL6_1_P527" (solid, pour order 527): 810.46,2715.04 828.91,2715.04 834,2720.14 834,2783.56 795.92,2821.64 795.92,2899.03 793.51,2901.44 782.43,2901.44 779.99,2899 779.99,2824.77 779.99,2722.51 787.46,2715.04
NetL2_1 on L10-Bottom Layer "L10-BOTTOM_LAYER_NETL2_1_P523" (solid, pour order 523): 2180.26,2169.29 2285.95,2169.29 2292.23,2175.34 2292.23,2223.04 2285.71,2229.55 2208.57,2229.55 2201.51,2222.48 2201.51,2203.34 2183.39,2185.22 2106,2185.22 2103.59,2182.81 2103.59,2171.73 2106.03,2169.29
NetC63_1 on L10-Bottom Layer "L10-BOTTOM_LAYER_NETC63_1_P522" (solid, pour order 522): 2107.38,2165.29 2173.04,2165.29 2198.46,2139.88 2198.46,2069.26 2195.46,2066.26 2153.76,2066.29 2147.76,2072.29 2147.76,2132.65 2130.13,2150.29 2107.47,2150.29 2103.46,2154.29 2103.46,2161.68
VBAT on L10-Bottom Layer "L10-BOTTOM_LAYER_VBAT_P520" (solid, pour order 520): 2227.32,2121.3 2214.46,2108.44 2214.46,2068.98 2227.71,2055.73 2271.12,2055.73 2286.46,2071.06 2286.46,2109.07 2274.24,2121.3
Net1.35V_1 on L10-Bottom Layer "L10-BOTTOM_LAYER_NET1.35V_1_P519" (solid, pour order 519): 2143.35,2251.35 2206.85,2251.35 2291.62,2251.35 2302,2261.73 2302,2401 2292,2411 2243,2411 2182,2350 2120.83,2350 2108.59,2337.76 2108.59,2295.23 2096.5,2283.14 2088.5,2275.14 2088.5,2257.26 2094.41,2251.35
VBAT on L10-Bottom Layer "L10-BOTTOM_LAYER_VBAT_P518" (solid, pour order 518): 1072.41,2357.86 1085.27,2345 1124.73,2345 1131.57,2351.84 1131.57,2408.08 1122.65,2417 1084.64,2417 1072.41,2404.78
NetC120_1 on L10-Bottom Layer "L10-BOTTOM_LAYER_NETC120_1_P517" (solid, pour order 517): 785,2238.52 794.52,2229 858.6,2229 868.46,2239.54 868.46,2319.55 845.07,2342.93 810.96,2342.93 785,2316.97
Net1.1V_1 on L10-Bottom Layer "L10-BOTTOM_LAYER_NET1.1V_1_P516" (solid, pour order 516): 955.57,2308.35 946.93,2316.99 946.93,2433.26 935.41,2444.79 899.37,2444.79 760.77,2444.79 736.86,2420.88 736.86,2376.14 760.91,2352.09 847.45,2352.09 886.06,2313.48 886.06,2272.05 898.76,2259.35 946.57,2259.35 955.57,2268.35
NetC19_2 on L10-Bottom Layer "L10-BOTTOM_LAYER_NETC19_2_P503" (solid, pour order 503): 900.61,1866.89
no net on L10-Bottom Layer "L10-BOTTOM_LAYER_NONET_P514" (solid, pour order 514): 818,2727.11
GND on L1-Top Layer "L1-TOP_LAYER_GND_P593" (solid, remove dead copper, pour order 593): 478,37 86,37 26,97 26,4076 114,4164 2269,4164 2337,4096 2337,83 2290,36
V_POWER on L1-Top Layer "L1-TOP_LAYER_V_POWER_P574" (solid, pour order 574): 2077,3511 2088,3500 2139,3500 2165.4,3526.4 2165.4,3536.9 2174.5,3546 2226,3546 2239.81,3559.81 2239.81,3748.99 2211.98,3776.82 2123.57,3776.82 2077,3730.25
V_VBAT on L1-Top Layer "L1-TOP_LAYER_V_VBAT_P555" (solid, pour order 555): 509.62,3309.69 512.65,3306.85 571.57,3306.85 595.48,3330.76 595.48,3529.46 603.24,3537.22 603.24,3579.76 596.13,3586.87 529.62,3586.87 509.62,3566.86
VUSB_5V on L1-Top Layer "L1-TOP_LAYER_VUSB_5V_P557" (solid, pour order 557): 34 vertices, not listed, extent 635.77,3500.57 1345,4009
VBAT on L1-Top Layer "L1-TOP_LAYER_VBAT_P556" (solid, pour order 556): 21 vertices, not listed, extent 554.37,3559.66 903.42,3789
V1P35_OV on L1-Top Layer "L1-TOP_LAYER_V1P35_OV_P586" (solid, pour order 586): 1490.3,2115 1480.74,2124.56 1480.74,2167.41 1485.33,2172 1583.49,2172 1596.71,2185.22 1681.67,2185.22 1696,2170.9 1696,2124 1687,2115 1592,2115
V3P3_MCU on L1-Top Layer "L1-TOP_LAYER_V3P3_MCU_P588" (solid, pour order 588): 1158.95,624.44 1158.95,572.44 1134.95,548.44 1134.95,539.44 1130.95,535.44 1107.34,535.44 1102.95,539.83 1102.95,633.44 1110.95,641.44 1149.95,641.44 1158.95,632.44
NetC15_2 on L1-Top Layer "L1-TOP_LAYER_NETC15_2_P525" (solid, pour order 525): 553.26,2203.1 553.26,2166.4 561.87,2157.79 619.67,2157.79 644.92,2132.54 644.92,1983.98 652.2,1976.7 916.48,1976.7 926.43,1986.66 926.43,2113.85 913.5,2126.79 776.53,2126.79 700.76,2202.56
Net2.5V_1 on L1-Top Layer "L1-TOP_LAYER_NET2.5V_1_P524" (solid, remove dead copper, pour order 524): 1156.89,2177.52 1161.01,2181.64 1201.91,2181.64 1247.12,2136.44 1247.12,2072.85 1234.79,2060.53 1186.37,2060.53 1177.25,2051.41 1177.25,2031.19 1167.24,2031.19 1156.89,2041.54
VBAT_Primary on L1-Top Layer "L1-TOP_LAYER_VBAT_PRIMARY_P547" (solid, pour order 547): 171.12,3417.15 171.12,3377.53 206.33,3342.31 362.77,3342.31 413.52,3393.07 495.77,3393.07 498.76,3396.06 498.76,3442.27 496.19,3444.83 399.91,3444.83 342.04,3386.96 281.16,3387 228.93,3439.23 193.2,3439.23
NetQ1_1 on L1-Top Layer "L1-TOP_LAYER_NETQ1_1_P548" (solid, pour order 548): 440.8,3349.8 388.62,3297.62 388.62,3254.21 393.84,3248.99 435.76,3248.99 443.39,3256.63 443.39,3290.93 462.14,3309.67 462.14,3343.29 455.63,3349.8
V1P1_OV on L1-Top Layer "L1-TOP_LAYER_V1P1_OV_P549" (solid, remove dead copper, pour order 549): 1329.86,2196.49 1356.98,2196.49 1375.91,2177.57 1375.91,2172.32 1388.2,2160.02 1388.2,2032.49 1384.02,2028.31 1341.55,2028.32 1336.38,2033.49 1336.38,2156.47 1329.86,2162.99
NetC27_1 on L1-Top Layer "L1-TOP_LAYER_NETC27_1_P551" (solid, remove dead copper, pour order 551): 1156.89,2009.31 1156.89,1989.86 1165.13,1981.62 1165.13,1885.41 1174.04,1876.5 1204.47,1876.5 1212.45,1884.48 1212.45,1982.93 1177.83,2017.55 1165.13,2017.55
V3P3_PA on L1-Top Layer "L1-TOP_LAYER_V3P3_PA_P584" (solid, pour order 584): 18 vertices, not listed, extent 480.67,1807 641,2002.26
V3P3_MCU on L1-Top Layer "L1-TOP_LAYER_V3P3_MCU_P590" (solid, pour order 590): 271.78,643.2 235,605.74 235,518.7 319.7,434 469,434 477,442 477,491 469,499 340,499 332,507 332,641.2 330,643.2
VDDAO on L1-Top Layer "L1-TOP_LAYER_VDDAO_P587" (solid, pour order 587): 1262.5,2601.1 1262.5,2683.68 1268.05,2689.24 1308.38,2689.24 1314.5,2683.12 1314.5,2603.41 1305.19,2594.1 1269.5,2594.1
AGND on L1-Top Layer "L1-TOP_LAYER_AGND_P585" (solid, pour order 585): 340.91,1940.55 336.25,1935.89 322.75,1935.89 318.09,1940.55 318.09,1947.71 325.38,1955 395.38,1955 402.38,1962 415.03,1962 418.03,1959 418.03,1946.44 412.14,1940.55
NetCN8_2 on L1-Top Layer "L1-Top Layer-NetCN15_2" (solid, pour order 589): 27 vertices, not listed, extent 1439.54,3120 1932,3814.95
NetC60_2 on L1-Top Layer "L1-TOP_LAYER_NETC60_2_P581" (solid, pour order 581): 2196.5,3275.5 2191,3270 2191,3178 2195,3174 2196,3175 2272,3175 2282,3185 2282,3252.13 2258.63,3275.5
VBAT on L1-Top Layer "L1-TOP_LAYER_VBAT_P573" (solid, pour order 573): 20 vertices, not listed, extent 2112,3410 2279,3505
NetC55_1 on L1-Top Layer "L1-TOP_LAYER_NETC55_1_P565" (solid, pour order 565): 1821,3364.7 1821,3299 1849,3271 1926.33,3271 1937,3281.67 1937,3372 1925,3384 1840.3,3384
NetC43_1 on L1-Top Layer "L1-TOP_LAYER_NETC43_1_P564" (solid, pour order 564): 24 vertices, not listed, extent 1516.96,3461 1930,3811
VREF on L1-Top Layer "L1-TOP_LAYER_VREF_P562" (solid, pour order 562): 23 vertices, not listed, extent 2057,3162 2181,3335
FB on L1-Top Layer "L1-TOP_LAYER_FB_P560" (solid, pour order 560): 1998,3237.25 1998,3141 1992,3135 1952.5,3135 1947,3140.5 1947,3256 1947,3398 2048,3398 2062,3384 2062,3244.5 2054.76,3237.26
SW on L1-Top Layer "L1-TOP_LAYER_SW_P559" (solid, pour order 559): 1845,3536 1952,3536 1978.2,3562.2 1978.2,3647.2 1987,3656 2027,3656 2035,3648 2035,3523 2052.07,3505.93 2052.07,3453.07 2047.26,3448.26 1859.74,3448.26 1845,3463
GND on L1-Top Layer "L1-TOP_LAYER_GND_P553" (solid, pour order 553): 683.24,2587.06 732.16,2587.06 739.03,2580.19 739.03,2567.03 735.79,2563.79 698.12,2563.79 678,2543.67 678,2532.9 669.9,2524.8 663,2524.8 620.98,2524.8 613,2532.79 613,2567.79 620.63,2575.42 671.59,2575.42
Net3.3V_1 on L1-Top Layer "L1-TOP_LAYER_NET3.3V_1_P554" (solid, pour order 554): 851,2569.79 978.38,2569.79 997.17,2551 1085.65,2551 1102.74,2568.09 1102,2583 1102,2619.79 1087.26,2634.52 1000.48,2634.52 1000,2635 787.98,2635 781.98,2629 781.98,2574.02 786.21,2569.79
V3P3A on L1-Top Layer "L1-TOP_LAYER_V3P3A_P552" (solid, pour order 552): 733.1,2591 614.79,2591 603,2602.79 603,2647.44 612.56,2657 723,2657 738.16,2641.84 738.16,2596.06
no net on L3-SIG1 "L3-SIG1-No Net" (solid, pour order 568): 289,1445
V3P3_MCU on L6-PWR "L6-PWR-V3P3_MCU" (solid, remove dead copper, pour order 611): 33 vertices, not listed, extent 26,89 2313,3854
V1P8 on L6-PWR "L6-PWR-V1P8" (solid, pour order 606): 22 vertices, not listed, extent 1015,1955.22 2321,3063.94
V1P8_OV on L6-PWR "L6-PWR_V1P8_OV_P607" (solid, remove dead copper, pour order 607): 33 vertices, not listed, extent 284,1265 1786.94,3331.85
no net on L6-PWR "Signal 3-No Net" (solid, remove dead copper, pour order 649): 6631.71,2045.24
no net on L6-PWR "L6-PWR-No Net" (solid, remove dead copper, pour order 600): 1439.54,2494
GND on L2-GND "L2-GND_GND_P576" (solid, remove dead copper, pour order 576): 470,23 78,23 18,83 18,4062 106,4150 2261,4150 2329,4082 2329,69 2282,22
AGND on L2-GND "L2-GND_AGND_P575" (solid, remove dead copper, pour order 575): 20 vertices, not listed, extent 287.38,1816 605.38,2094.98
VBAT on L8-SIG2 "L8-SIG2_VBAT_P571" (solid, remove dead copper, pour order 571): 72 vertices, not listed, extent 276,871 2340,3830
V1P8_SN_DVDD on L8-SIG2 "L8-SIG2_V1P8_SN_DVDD_P592" (solid, pour order 592): 947.93,3003.18 956.11,2995 956.11,2929.67 968.78,2917 1579.88,2917 1604.03,2941.15 1604.03,3224.33 1557.36,3271 738,3271 722.42,3255.42 722.42,3022.45 741.95,3003.18
V_VBAT on L8-SIG2 "L8-SIG2_V_VBAT_P578" (solid, remove dead copper, pour order 578): 25 vertices, not listed, extent 31,3244 1002,3827
DDR_VREF on L8-SIG2 "L8-SIG2_DDR_VREF_P570" (solid, remove dead copper, pour order 570): 1571.96,2135.04 1568.56,2138.44 1568.56,2293.59 1614.72,2339.75 1650,2339.6 1960.4,2339.6 1968,2332 1968,2309.87 1968,2149.75 1937.5,2119.26 1696.06,2119.26 1587.74,2119.26
V3P3 on L5-PWR "L5-PWR_V3P3_P602" (solid, remove dead copper, pour order 602): 47 vertices, not listed, extent 9,2446 2337,4139
V3P3A on L5-PWR "L5-PWR-V3P3A 1" (solid, remove dead copper, pour order 610): 33 vertices, not listed, extent 15,33 2332.12,2657
V3P3_OV on L5-PWR "L5-PWR_V3P3_OV_P601" (solid, remove dead copper, pour order 601): 38 vertices, not listed, extent 1147.61,2343.2 1766,2721.82
V1P35 on L5-PWR "L5-PWR-V1P35" (solid, remove dead copper, pour order 609): 2039,2507.65 2058.65,2527.31 2313.83,2527.31 2329,2514.04 2329,1954 2298,1923 1646,1923 1634,1935 1634,2102.65 1649.01,2117.67 2007.32,2117.67 2039,2149.35
V1P1_OV on L5-PWR "L5-PWR_V1P1_OV_P603" (solid, remove dead copper, pour order 603): 41 vertices, not listed, extent 1272.09,1971.6 1612,2554.14
V1P1 on L5-PWR "L5-PWR_V1P1_P605" (solid, pour order 605): 658.09,2315.43 658.09,1921.91 683.3,1896.7 1242.14,1896.7 1261.85,1916.41 1261.85,2296.68 1222.31,2336.22 754.78,2336.22 723.54,2367.46 723.54,2431.99 713.53,2442 665,2442 658.09,2435.09
V1P35_OV on L5-PWR "L5-PWR_V1P35_OV_P604" (solid, remove dead copper, pour order 604): 1718.46,2346 1752.64,2346 1770.15,2363.51 1972.02,2363.51 1981,2354.53 1981,2151 1970,2140 1912.49,2140 1586.88,2140 1574,2152.88 1574,2175.77 1574,2287 1554.95,2306.05 1554.95,2333.77 1567.18,2346
V3P3_SC on L5-PWR "L5-PWR-V3P3_SC" (solid, remove dead copper, pour order 612): 135,3015.78 140.22,3021 164.61,3021 170.85,3027.24 170.85,3227.84 176,3233.76 359.62,3233.76 368,3225.38 368,2835.93 353.07,2821 148,2821 135,2834
V3P3_Amp on L5-PWR "L5-PWR-V3P3_Amp" (solid, remove dead copper, pour order 608): 505.38,3191 455.43,3191 433.99,3212.44 433.99,3651.39 419.45,3665.93 198.07,3665.93 192,3672 192,3810.37 204.48,3822.85 625.15,3822.85 663.13,3784.87 663.13,3469.87 663.3,3200.7 653.59,3191
GND on L4-GND "L4-GND_GND_P619" (solid, remove dead copper, pour order 619): 470,23 78,23 18,83 18,4062 106,4150 2261,4150 2329,4082 2329,69 2282,22
AGND on L4-GND "L4-GND_AGND_P617" (solid, remove dead copper, pour order 617): 20 vertices, not listed, extent 287.38,1816 605.38,2094.98
GND on L7-GND "L7-GND_GND_P623" (solid, remove dead copper, pour order 623): 470,23 78,23 18,83 18,4062 106,4150 2261,4150 2329,4082 2329,69 2282,22
AGND on L7-GND "L7-GND_AGND_P621" (solid, remove dead copper, pour order 621): 20 vertices, not listed, extent 287.38,1816 605.38,2094.98
GND on L9-GND "L9-GND_GND_P627" (solid, remove dead copper, pour order 627): 470,23 78,23 18,83 18,4062 106,4150 2261,4150 2329,4082 2329,69 2282,22
AGND on L9-GND "L9-GND_AGND_P625" (solid, remove dead copper, pour order 625): 20 vertices, not listed, extent 287.38,1816 605.38,2094.98

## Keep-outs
Keep-Out Layer:
  text ".Layer_Name" at 514.83,-897.86 h60

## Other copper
L1-Top Layer:
  pour cut-out: 2113.5,3500 2108.25,3494.75 2108.25,3471.2 2111.83,3467.63 2173.38,3467.63 2180.75,3475 2180.75,3515.25 2177,3519 2158,3519 2138.17,3499.17 2114.32,3499.17
  pour cut-out: 2227.83,3393.51 2227.83,3407.67 2222.89,3412.61 2186.58,3412.61 2177.98,3404 2177.98,3393.02 2189,3382 2217.05,3382 2217.05,3382.73
  pour cut-out: 375.63,2092.81 287.53,2092.81 271.63,2076.91 271.63,1838.57 273.94,1836.26 368.68,1836.26 368.68,1900.05 341,1927.73 316.27,1927.73 307,1937 307,1956.52 313.63,1963.16 338.35,1963.16 340.7,1965.5 340.7,1998.7 344.09,2002.09 382.41,2002.09 389,2008.69 389,2079.44
  pour cut-out: 522.25,2096.57 569.75,2096.57 571.22,2095.1 571.22,2004.3 525.72,2004.3 522.25,2007.77
  pour cut-out: 522.25,2097.79
  pour cut-out: 473.63,1886.02 473.63,1819.6 478.23,1815 530.11,1815 535,1819.89 535,1879 525,1889 476.61,1889
  pour cut-out: 26,1640.24 87.32,1640.24 97.07,1630.5 97.07,1615.07 68.75,1586.75 68.75,1515.75 59.86,1506.86 23.14,1506.86 18,1512 18,1632.24
  pour cut-out: 26,1797.74 91.26,1797.74 100.31,1788.69 100.31,1695.23 92.32,1687.25 26,1687.25
  pour cut-out: 25.31,2637.31 21,2633 21,2363.29 27.15,2357.14 89.11,2357.14 89.11,2448.89 98.5,2458.27 118.27,2458.27 125.28,2465.28 125.28,2512.96 93.08,2545.16 93.08,2630.23 86,2637.31
  pour cut-out: 938.46,3219 938.46,3256.07 927.54,3267 800.58,3267 785.74,3252.16 785.74,3160.36 741.63,3116.25 741.63,3074.09 748.6,3067.12 896.89,3067.12 907.07,3077.31 907.07,3188.3 936.7,3217.93
  pour cut-out: 882.23,3055.87 882.23,2983.99 889.69,2976.53 898.69,2976.53 898.69,3057.59 895.14,3061.14 885.35,3061.14 882,3057.79
  pour cut-out: 2067.66,2395.34 2076,2387 2076,2243.72 2040.26,2207.98 1900.7,2207.98 1900.7,2299.21 1919.5,2318 1958.31,2318 2035.65,2395.34
  pour cut-out: 1495,2001.54 1495,1943.5 1500.5,1938 1509.5,1938 1509.5,1988.25 1495.75,2002
  pour cut-out: 679.22,1746.97 680.76,1748.51 680.76,1760 668.95,1760 666.99,1758.04 666.99,1789.67 652.66,1804 647.04,1809.35 635.35,1809.35 628,1802 595,1802 577.86,1819.14 561,1819.14 560,1819.46 560,1756.25 569.28,1746.97
  pour cut-out: 1365.39,304.19
  pour cut-out: 1185.76,584.14 1320.19,584.14 1339.06,565.28 1339.06,470.06 1336,467 1268,467 1267,468 1189.52,468 1176,481.52 1176,574.39
  pour cut-out: 1193.76,2364 1158,2364 1149.65,2372.35 1155.54,2378.25 1155.54,2388.57 1166.66,2399.69 1190.57,2399.69 1196.17,2394.09 1196.17,2382
  pour cut-out: 1636,2032.49 1636,2104.65 1641.51,2110.16 1686.96,2110.16 1696.06,2119.26 1746.74,2119.26 1759.27,2106.73 1777.27,2106.73 1791,2093 1791,2043.79 1779.14,2031.93 1773.93,2031.93 1771,2029 1773.32,2026.68 1773.32,2004.96 1647.04,2004.96 1637,2015 1637,2031.26 1629.53,2038.73
  pour cut-out: 1843,1544.14 1934.9,1544.14 1955.28,1523.76 2181.51,1523.76 2199.77,1505.49 2199.77,1269.07 2206.37,1262.47 2238.53,1262.47 2254.18,1278.12 2254.18,1302.12 2308.75,1356.68 2308.75,1614.07 2271.82,1651 1839.13,1651 1827,1638.87 1827,1548.58 1831.58,1544 1842.65,1544
  pour cut-out: 1870.51,2463.58 1870.51,2374.93 1863,2367.42 1762.56,2367.42 1736.65,2393.33 1736.65,2505.51 1740.75,2509.61 1760.7,2509.61 1765,2505.3 1765,2483.6 1769.74,2478.86 1782,2478.86 1786.86,2474 1867.82,2474 1870.55,2471.27 1870.55,2463.86
  pour cut-out: 1600.51,2461.87 1600.51,2432.27 1613.6,2419.18 1653.72,2419.18 1660.51,2425.96 1660.51,2463.58 1653.72,2470.36 1604.21,2470.36 1600.27,2466.42
  pour cut-out: 1413.75,2602.4 1409.9,2598.54 1409.9,2567.34 1422.24,2555 1430,2555 1431.49,2556.49 1431.49,2576.95 1447,2592.46 1447,2596.89 1442.84,2592.73 1422.89,2592.73 1414,2601.62 1414,2602.35
  pour cut-out: 896.32,492 914,474.32 914,347.3 910.33,343.63 842.36,343.63 826.99,359 701,359 697,355 697,450 739,492
  pour cut-out: 697,355
  pour cut-out: 177,562.83 230.13,562.83 235,557.96 235,513.52 273,475.52 273,454 265,446 188.16,446 178.16,456 178.16,536.81 170,544.97 170,556.22 176,562.22
  pour cut-out: 503.32,521.8 503.32,348.55 516,335.87 678.17,335.87 721,378.7 721,520.21 709.21,532 513.52,532
  pour cut-out: 1932.55,1348.9 1932.55,1502.44 1976.11,1502.44 1976.11,1346.68 1934.77,1346.68
  pour cut-out: 1572.29,1474.04 1780.87,1474.04 1785.17,1469.75 1785.17,1305.49 1784.68,1305 1714.86,1305 1713.04,1303.18 1678.22,1338 1612.05,1338 1611.74,1406.03 1603.45,1414.31 1553.58,1414.31 1545.32,1422.57 1545.32,1471.26 1548.1,1474.04
  pour cut-out: 937,1377.98 966.3,1407.28 966.3,1446.3 993,1473 1385.29,1473 1394.29,1464 1394.29,1443.94 1178.24,1227.88 1178.24,1185 1186.87,1176.37 1200.18,1163.05 1200.18,770.87 1182.32,753 943.47,753 937,759.47
  pour cut-out: 233.92,3114.11 243.73,3114.11 252.64,3105.21 252.64,3081.84 244.62,3073.83 233.92,3073.83 233.92,3047.02 231.22,3044.32 231.22,2982.13 238.35,2975 278,2975 290,2987 290,3110.69 267.79,3132.9 267.79,3137 241.3,3137 233.92,3129.62
  pour cut-out: 257.24,2932 257.24,2917.62 212,2872.38 212,2685.3 227.3,2670 603.57,2670 626,2692.43 626,2767.3 598.73,2794.57 522,2794.57 442.56,2874.01 408.08,2874.01 342.39,2939.69 264.69,2939.69 258,2933
  pour cut-out: 1596.39,2524.27 1603.66,2517 1669.59,2517 1679,2526.41 1679,2616.52 1588.52,2707 1535.61,2707 1525.78,2697.17 1525.78,2610.66 1542.3,2594.14 1580.87,2594.14 1596.74,2578.27 1596.74,2524.8
  pour cut-out: 1470.58,2620.21 1470.58,2717.81 1473.78,2721 1499.93,2721 1507,2713.93 1507,2629.76 1496.59,2619.35 1472.59,2619.35
  pour cut-out: 1193.24,2534.3 1207.64,2548.7 1207.64,2574.12 1237.75,2604.22 1237.75,2714.61 1242,2718.86 1316.53,2718.86 1319,2716.39 1319,2694.47 1316.53,2692 1260.16,2692 1254.96,2686.8 1254.96,2592.96 1244,2582 1244,2574.35 1203.95,2534.3
  pour cut-out: 1377.08,2721 1380,2718.08 1380,2689 1374.42,2683.42 1349.08,2683.42 1335,2697.5 1335,2716 1340,2721
  pour cut-out: 1644.53,2342.41 1644.53,2326.01 1656.71,2313.83 1671,2313.83 1671,2311.98 1681.67,2301.31 1681.67,2288.37 1675.15,2281.84 1671.52,2281.84 1671.52,2272.47 1680.35,2263.64 1696.86,2263.64 1702,2268.78 1722.97,2268.78 1732.5,2278.31 1732.5,2351.03 1725.53,2358 1655.01,2358 1645.08,2348.08 1645.08,2345.21
  pour cut-out: 1493.68,2315.54 1493.68,2272.14 1500.18,2265.64 1602.54,2265.64 1606.36,2269.45 1606.36,2313 1602.54,2316.82 1586.82,2316.82 1580.32,2310.32 1523.98,2310.32 1517.66,2316.64 1494.89,2316.64 1493.68,2315.43
  pour cut-out: 1255.41,2517 1244,2505.59 1244,2252.19 1260,2236.19 1470.74,2236.19 1475.54,2240.99 1475.54,2314.28 1438.47,2351.35 1438.47,2480.89 1397.79,2521.57 1259.72,2521.57 1255.41,2517.26
  text ".Layer_Name" at 514.83,-897.86 h60
L2-GND:
  text ".layer_name" at 592,-900 h60
L3-SIG1:
  text ".layer_name" at 665,-896 h60
L4-GND:
  text ".layer_name" at 694,-889 h60
L5-PWR:
  text ".layer_name" at 705,-887 h60
L6-PWR:
  text ".layer_name" at 668,-883 h60
L7-GND:
  text ".layer_name" at 673,-888 h60
L8-SIG2:
  text ".layer_name" at 687,-888 h60
L9-GND:
  text ".layer_name" at 665,-894 h60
